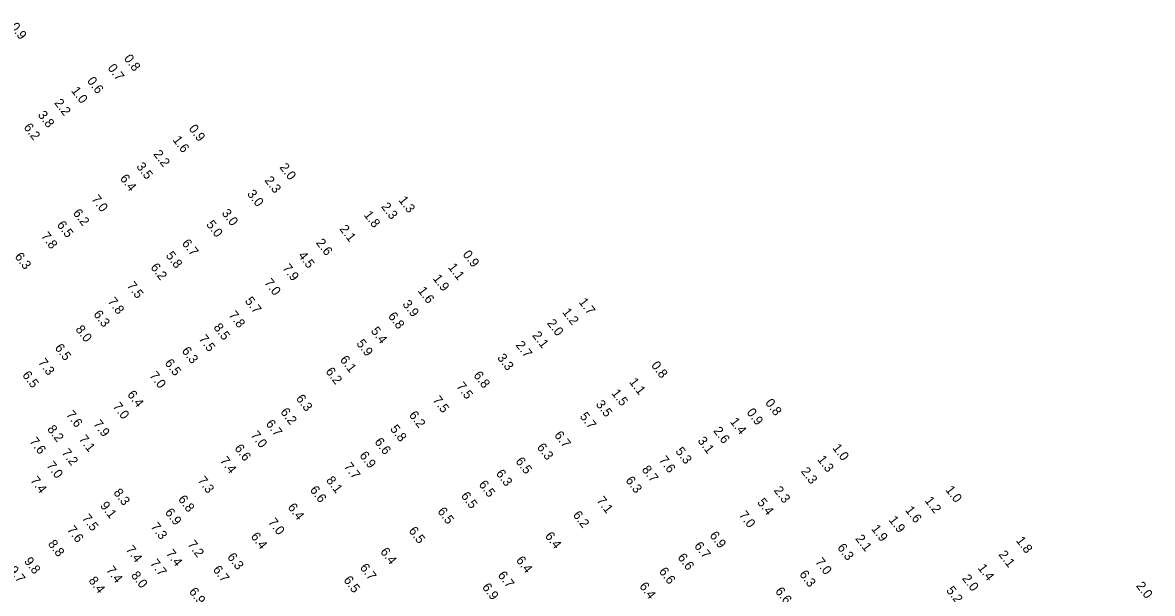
# Model space of a CAD drawing. Extents: x 815385 to 820851, y 582449 to 604245.
# Drawn here: x 818415 to 819025, y 595182 to 595490 of the extents above; entities that cross this region are included whole.
import ezdxf

# ---------------------------------------------------------------- set-up
doc = ezdxf.new("R2010")
doc.units = 0
for name, color, linetype in [('V-TOPO-SOUN-011609', 7, 'Continuous'), ('V-TOPO-SOUN-020509C', 7, 'Continuous'), ('V-TOPO-SOUN-EXCSS', 7, 'Continuous')]:
    doc.layers.add(name, color=color, linetype=linetype)

msp = doc.modelspace()

# ---------------------------------------------------------------- texts
at = {"layer": 'V-TOPO-SOUN-011609'}
for s, p in [('0.9', (818408.09, 595487.66)), ('0.8', (818469.51, 595470.5)), ('0.7', (818460.73, 595465.37)), ('0.6', (818449.59, 595458.38)), ('1.0', (818441.03, 595453.12)), ('2.2', (818431.91, 595446.53)), ('3.8', (818423.02, 595440.04)), ('6.2', (818415.36, 595433.34)), ('0.9', (818504.52, 595432.62)), ('1.6', (818495.86, 595426.54)), ('2.2', (818485.45, 595418.88)), ('3.5', (818476.22, 595412.18)), ('2.0', (818553.59, 595411.78)), ('6.4', (818467.35, 595405.75)), ('2.3', (818545.49, 595404.68)), ('7.0', (818451.95, 595394.55)), ('3.0', (818536.08, 595397.41)), ('1.3', (818617.88, 595394.02)), ('6.2', (818441.97, 595387.04)), ('3.0', (818522.31, 595387.01)), ('2.3', (818608.49, 595390.54)), ('6.5', (818433.31, 595380.65)), ('5.0', (818513.97, 595380.87)), ('1.8', (818599.08, 595386.04)), ('7.8', (818424.72, 595374.57)), ('2.1', (818585.95, 595378.47)), ('6.7', (818500.86, 595370.71)), ('2.6', (818573.26, 595370.99)), ('6.3', (818410.52, 595363.52)), ('5.8', (818492.17, 595364.09)), ('4.5', (818563.6, 595364.09)), ('0.9', (818652.52, 595364.7)), ('6.2', (818483.88, 595357.75)), ('7.9', (818555.14, 595357.3)), ('1.1', (818644.6, 595357.75)), ('7.0', (818545.33, 595349.43)), ('1.9', (818636.4, 595351.74)), ('7.5', (818471.18, 595347.82)), ('1.6', (818628.25, 595345.08)), ('7.8', (818460.77, 595339.28)), ('5.7', (818534.86, 595339.58)), ('3.9', (818619.98, 595337.82)), ('1.7', (818715.17, 595338.99)), ('6.3', (818453.05, 595332.36)), ('7.8', (818526.09, 595331.93)), ('1.2', (818706.29, 595333.53)), ('6.8', (818612.21, 595331.33)), ('2.0', (818698.07, 595327.56)), ('8.0', (818443.34, 595324.23)), ('7.5', (818509.96, 595319.09)), ('8.5', (818517.92, 595325.3)), ('5.4', (818602.89, 595323.36)), ('2.1', (818690.09, 595320.97)), ('6.5', (818432.16, 595314.25)), ('5.9', (818595.11, 595316.62)), ('2.7', (818681.13, 595315.78)), ('6.3', (818500.76, 595312.63)), ('6.1', (818586.2, 595307.84)), ('3.3', (818671.17, 595308.91)), ('7.3', (818423.14, 595306.33)), ('6.5', (818491.53, 595306.04)), ('6.2', (818578.46, 595301.49)), ('0.8', (818754.33, 595304.78)), ('6.5', (818414.6, 595299.51)), ('7.0', (818483.34, 595299.27)), ('6.8', (818658.36, 595299.39)), ('1.1', (818742.43, 595295.82)), ('6.4', (818471.31, 595289.04)), ('7.5', (818649.15, 595293.46)), ('1.5', (818732.89, 595289.78)), ('7.0', (818463.49, 595282.6)), ('6.3', (818562.46, 595286.87)), ('7.5', (818636.27, 595286.04)), ('3.5', (818724.42, 595283.79)), ('0.8', (818815.92, 595284.51)), ('6.2', (818554.03, 595279.62)), ('6.2', (818623.49, 595277.92)), ('5.7', (818715.75, 595277.26)), ('0.9', (818805.9, 595279.39)), ('7.9', (818452.95, 595273.11)), ('6.7', (818546.14, 595273.26)), ('5.8', (818613.31, 595270.48)), ('1.4', (818796.95, 595274.37)), ('7.1', (818445.15, 595264.98)), ('7.0', (818537.99, 595267.11)), ('6.7', (818702, 595267.1)), ('2.6', (818787.89, 595269.46)), ('6.6', (818529.22, 595260)), ('6.6', (818604.87, 595263.48)), ('6.3', (818692.59, 595260.54)), ('5.3', (818767.43, 595258.42)), ('3.1', (818779.42, 595264.08)), ('1.0', (818852.25, 595260.21)), ('7.2', (818435.85, 595257.62)), ('7.4', (818521.4, 595253.29)), ('6.9', (818596.75, 595256.11)), ('6.5', (818681.09, 595253)), ('7.6', (818758.54, 595253.64)), ('1.3', (818844.1, 595253.97)), ('7.0', (818427.69, 595250.67)), ('7.7', (818588.31, 595250.17)), ('6.3', (818670.46, 595246.38)), ('8.7', (818749.27, 595248.51)), ('2.3', (818835.21, 595247.58)), ('7.4', (818418.96, 595242.61)), ('7.3', (818509.35, 595242.63)), ('8.1', (818578.73, 595242.71)), ('6.5', (818661.19, 595240.47)), ('6.3', (818740.5, 595242.67)), ('6.6', (818569.97, 595237.54)), ('6.5', (818651.58, 595234.31)), ('2.3', (818820.59, 595237.3)), ('1.0', (818913.3, 595237.59)), ('6.8', (818498.77, 595232.48)), ('6.4', (818557.99, 595228.15)), ('7.1', (818724.86, 595231.79)), ('5.4', (818811.63, 595230.79)), ('1.2', (818902.1, 595231.77)), ('6.9', (818491.71, 595225.39)), ('6.5', (818638.92, 595225.94)), ('6.2', (818712, 595223.97)), ('7.0', (818801.71, 595223.95)), ('1.6', (818891.54, 595226.62)), ('7.3', (818484, 595217.65)), ('7.0', (818547.43, 595220.12)), ('1.9', (818873.23, 595216.54)), ('1.9', (818882.68, 595221.31)), ('6.4', (818538.03, 595212.41)), ('6.5', (818623.33, 595215.46)), ('6.4', (818696.96, 595212.65)), ('6.9', (818785.89, 595212.94)), ('2.1', (818864.64, 595211.23)), ('1.8', (818951.41, 595210.2)), ('7.4', (818470.52, 595205.29)), ('6.4', (818608, 595204.16)), ('6.7', (818777.57, 595207.31)), ('6.3', (818854.87, 595206.35)), ('6.3', (818525.33, 595201.31)), ('6.4', (818681.3, 595199.55)), ('6.6', (818768.59, 595201.05)), ('7.0', (818842.95, 595198.65)), ('2.1', (818941.98, 595202.64)), ('7.4', (818459.9, 595194.2)), ('6.7', (818517.53, 595194.47)), ('6.7', (818596.98, 595195.57)), ('6.7', (818671.46, 595191.44)), ('6.6', (818758.53, 595193.52)), ('6.3', (818834.38, 595191.96)), ('1.4', (818930.75, 595195.39)), ('8.4', (818450.44, 595188.57)), ('6.5', (818588.16, 595188.85)), ('6.4', (818747.96, 595185.51)), ('2.0', (818922.32, 595189.7)), ('2.0', (819016.27, 595185.74)), ('6.9', (818504.66, 595182.61)), ('6.9', (818662.99, 595184.99)), ('6.6', (818821.32, 595182.82)), ('5.2', (818913.73, 595183.27))]:
    msp.add_text(s, height=5, rotation=307.782, dxfattribs=at).set_placement(p)
at = {"layer": 'V-TOPO-SOUN-020509C'}
for s, p in [('9.8', (818415.58, 595199.02)), ('9.7', (818407.31, 595194.23))]:
    msp.add_text(s, height=5, rotation=307.782, dxfattribs=at).set_placement(p)
at = {"layer": 'V-TOPO-SOUN-EXCSS'}
for s, p in [('7.6', (818438.25, 595278.18)), ('8.2', (818428.08, 595270.33)), ('7.6', (818418.49, 595263.72)), ('8.3', (818463.88, 595236.06)), ('9.1', (818456.65, 595229.04)), ('7.5', (818446.85, 595222.24)), ('7.6', (818438.77, 595216.01)), ('8.8', (818428.48, 595208.38)), ('7.4', (818492.21, 595203.14)), ('7.2', (818503.86, 595208.09)), ('7.7', (818483.68, 595197.86)), ('8.0', (818473.35, 595191.35))]:
    msp.add_text(s, height=5, rotation=307.782, dxfattribs=at).set_placement(p)

doc.saveas('drawing.dxf')
